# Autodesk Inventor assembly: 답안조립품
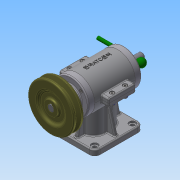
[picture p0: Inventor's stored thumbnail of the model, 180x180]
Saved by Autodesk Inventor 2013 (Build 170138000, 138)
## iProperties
Created: 2015-12
Part Number: 답안조립품
Document SubType Name: Assembly
Designer: Administrator
Mass: 1960.53 g
Surface Area: 1487.03 cm^2
Volume: 472.442 cm^3
Density: 4.14977 g/cm^3
Author: Administrator
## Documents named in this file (19)
- C:\Users\Administrator\Desktop\351208V1039\답안조립품.iam
- C:\Users\Administrator\Desktop\351208V1039\본체.ipt
- C:\Users\Administrator\Desktop\351208V1039\V-벨트풀리.ipt
- C:\Users\Administrator\Desktop\351208V1039\너트 M4.ipt
- C:\Users\Administrator\Desktop\351208V1039\뒤커버.ipt
- C:\Users\Administrator\Desktop\351208V1039\레바.ipt
- C:\Users\Administrator\Desktop\351208V1039\멈춤나사 M3x8.ipt
- C:\Users\Administrator\Desktop\351208V1039\베어링 6201.ipt
- C:\Users\Administrator\Desktop\351208V1039\베어링 6202.ipt
- C:\Users\Administrator\Desktop\351208V1039\본체커버.ipt
- C:\Users\Administrator\Desktop\351208V1039\볼트 M3x0.5x8.ipt
- C:\Users\Administrator\Desktop\351208V1039\볼트 M4 x 16.ipt
- C:\Users\Administrator\Desktop\351208V1039\슬라이드.ipt
- C:\Users\Administrator\Desktop\351208V1039\앞커버.ipt
- C:\Users\Administrator\Desktop\351208V1039\오일실 12 22 7.ipt
- C:\Users\Administrator\Desktop\351208V1039\와셔 ST 4-100.ipt
- C:\Users\Administrator\Desktop\351208V1039\키 4 x 4 x 18.ipt
- C:\Users\Administrator\Desktop\351208V1039\편심축.ipt
- C:\Users\Administrator\Desktop\351208V1039\스프링1.ipt
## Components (13 placed, 4 different names)
1. V-벨트풀리:1 — 플러쉬:1
2. ISO 4032 M4:1
3. ISO 4762 M4 x 16:1
4. ISO 7091 ST 4 - 100 HV:1
5. ISO 4762 M4 x 16:2
6. ISO 4762 M4 x 16:3
7. ISO 4762 M4 x 16:4
8. ISO 4032 M4:2
9. ISO 4032 M4:3
10. ISO 4032 M4:4
11. ISO 7091 ST 4 - 100 HV:2
12. ISO 7091 ST 4 - 100 HV:3
13. ISO 7091 ST 4 - 100 HV:4
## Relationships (1: Flush 1)
- 플러쉬:1 [Flush]: V-벨트풀리:1
